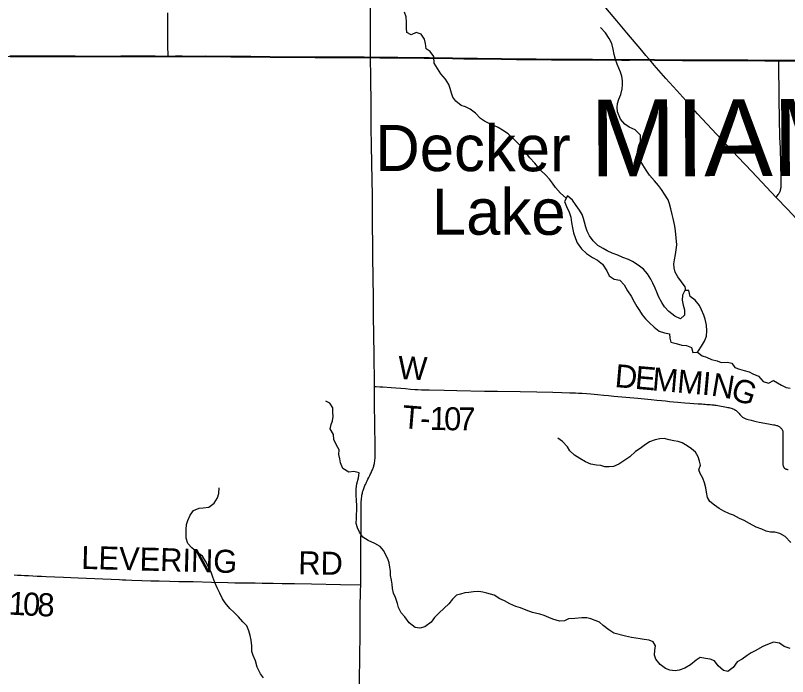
# Model space of a CAD drawing. Extents: x -87 to 2145, y -2128 to 440.
# Drawn here: x 138.4 to 188.6, y 171.2 to 214.2 of the extents above; entities that cross this region are included whole.
import ezdxf

# ---------------------------------------------------------------- set-up
doc = ezdxf.new("R2010")
doc.units = 0
for name, color, linetype in [('GM_X_County_Road', 7, 'Continuous'), ('GM_X_County_Text', 7, 'Continuous'), ('GM_X_Minor_Lake', 7, 'Continuous'), ('GM_X_Minor_Lake_Text', 7, 'Continuous'), ('GM_X_Minor_River', 7, 'Continuous'), ('GM_X_State_Route', 7, 'Continuous'), ('GM_X_Township', 7, 'Continuous'), ('GM_X_Township_Road', 7, 'Continuous'), ('GM_X_Township_Road_Text', 7, 'Continuous'), ('GM_X_Township_Text', 7, 'Continuous'), ('SH_Cut_Line', 7, 'Continuous')]:
    doc.layers.add(name, color=color, linetype=linetype)

msp = doc.modelspace()

# ---------------------------------------------------------------- linework, layer by layer
at = {"layer": 'GM_X_County_Road'}
for points in [[(135.03, 211.568), (135.109, 211.569), (135.519, 211.57), (136.027, 211.566), (136.749, 211.568), (137.175, 211.571), (138.012, 211.566), (139.406, 211.565), (140.879, 211.559), (141.702, 211.555), (142.26, 211.553), (143.31, 211.552), (143.851, 211.547), (144.229, 211.55), (145.229, 211.56), (146.869, 211.562), (147.46, 211.558), (148.231, 211.55), (148.289, 211.551)], [(148.289, 211.551), (148.772, 211.554), (149.215, 211.554), (149.92, 211.552), (150.707, 211.554), (151.199, 211.549), (151.495, 211.548), (151.986, 211.547), (152.38, 211.543), (153.167, 211.535), (153.676, 211.533), (154.446, 211.523), (154.922, 211.517), (156.07, 211.505), (156.726, 211.502), (157.055, 211.502), (157.858, 211.5), (158.498, 211.499), (159.383, 211.487), (159.679, 211.487), (160.17, 211.492), (160.563, 211.492), (161.039, 211.492), (161.46, 211.486)], [(161.46, 211.486), (161.728, 211.483), (162.056, 211.478), (162.81, 211.471), (163.236, 211.467), (163.58, 211.464), (163.859, 211.464), (164.411, 211.459), (164.941, 211.454), (165.284, 211.447), (166.794, 211.423), (167.519, 211.412), (168.248, 211.4), (168.428, 211.4), (168.576, 211.4), (169.133, 211.395), (169.986, 211.381), (170.954, 211.368), (171.381, 211.367), (171.807, 211.365), (172.233, 211.358), (172.643, 211.354), (173.234, 211.348), (173.955, 211.349), (174.349, 211.341), (174.857, 211.336), (175.891, 211.335), (176.547, 211.332), (177.285, 211.332), (177.793, 211.327), (178.302, 211.325), (179.335, 211.332), (179.466, 211.33), (179.622, 211.329)], [(179.622, 211.329), (179.927, 211.325), (181.221, 211.311), (181.745, 211.305), (182.189, 211.305), (182.664, 211.301), (183.533, 211.298), (184.222, 211.296), (185.075, 211.293), (186.01, 211.293), (187.109, 211.284), (187.732, 211.28), (188.051, 211.281)], [(188.051, 211.281), (188.323, 211.282), (189.323, 211.279), (190.176, 211.277), (191.259, 211.274), (192.243, 211.267), (192.834, 211.266), (193.572, 211.263), (194.31, 211.257), (194.654, 211.259)]]:
    msp.add_lwpolyline(points, dxfattribs=at)
at = {"layer": 'GM_X_Minor_Lake'}
for points in [[(175.368, 200.768), (175.314, 201.02), (175.219, 201.274), (175.054, 201.549), (174.829, 201.865), (174.586, 202.212), (174.26, 202.481), (174.071, 202.124), (174.214, 201.789), (174.387, 201.424), (174.48, 201.091), (174.533, 200.748), (174.596, 200.405), (174.669, 200.073), (174.792, 199.708), (174.906, 199.425), (175.169, 199.037), (175.514, 198.728), (175.901, 198.478), (176.219, 198.3), (176.555, 198.031), (176.817, 197.613), (176.971, 197.278), (177.308, 197.07), (177.679, 196.99), (177.954, 196.693), (178.166, 196.317), (178.41, 195.96), (178.603, 195.584), (178.787, 195.288), (178.943, 195.034), (179.127, 194.749), (179.343, 194.493), (179.589, 194.236), (179.904, 193.937), (180.23, 193.689), (180.57, 193.57), (180.91, 193.502), (180.934, 193.221), (180.999, 192.958), (181.339, 192.87), (181.698, 192.771), (182, 192.753), (182.339, 192.615), (182.412, 192.302), (182.734, 192.324)], [(182.734, 192.324), (182.796, 192.393), (182.994, 192.709), (183.172, 193.026), (183.3, 193.364), (183.338, 193.714), (183.306, 194.076), (183.224, 194.459), (183.129, 194.712), (182.976, 195.077), (182.852, 195.361), (182.567, 195.689), (182.241, 195.937), (182.169, 196.32), (181.908, 196.337), (181.74, 196.02), (181.723, 195.689), (181.786, 195.376), (181.87, 195.063), (181.882, 194.722), (181.626, 194.487), (181.247, 194.657), (180.852, 194.958), (180.587, 195.275), (180.402, 195.55), (180.219, 195.896), (180.085, 196.21), (179.97, 196.474), (179.816, 196.798), (179.681, 197.072), (179.468, 197.409), (179.213, 197.726), (178.867, 197.975), (178.5, 198.205), (178.241, 198.341), (177.872, 198.47), (177.533, 198.619), (177.184, 198.758), (176.846, 198.907), (176.588, 199.063), (176.25, 199.262), (175.935, 199.551), (175.691, 199.877), (175.557, 200.192), (175.462, 200.445), (175.368, 200.768), (175.314, 201.02), (175.219, 201.274), (175.054, 201.549), (174.829, 201.865), (174.586, 202.212), (174.26, 202.481), (174.071, 202.124), (174.214, 201.789), (174.387, 201.424), (174.48, 201.091), (174.533, 200.748), (174.596, 200.405), (174.669, 200.073), (174.792, 199.708), (174.906, 199.425), (175.169, 199.037), (175.514, 198.728), (175.901, 198.478), (176.219, 198.3), (176.555, 198.031), (176.817, 197.613), (176.971, 197.278), (177.308, 197.07), (177.679, 196.99), (177.954, 196.693), (178.166, 196.317), (178.41, 195.96), (178.603, 195.584), (178.787, 195.288), (178.943, 195.034), (179.127, 194.749), (179.343, 194.493), (179.589, 194.236), (179.904, 193.937), (180.23, 193.689), (180.57, 193.57), (180.91, 193.502), (180.934, 193.221), (180.999, 192.958), (181.339, 192.87), (181.698, 192.771), (182, 192.753), (182.339, 192.615), (182.412, 192.302), (182.734, 192.324)], [(182.734, 192.324), (182.796, 192.393), (182.994, 192.709), (183.172, 193.026), (183.3, 193.364), (183.338, 193.714), (183.306, 194.076), (183.224, 194.459), (183.129, 194.712), (182.976, 195.077), (182.852, 195.361), (182.567, 195.689), (182.241, 195.937), (182.169, 196.32), (181.908, 196.337), (181.74, 196.02), (181.723, 195.689), (181.786, 195.376), (181.87, 195.063), (181.882, 194.722), (181.626, 194.487), (181.247, 194.657), (180.852, 194.958), (180.587, 195.275), (180.402, 195.55), (180.219, 195.896), (180.085, 196.21), (179.97, 196.474), (179.816, 196.798), (179.681, 197.072), (179.468, 197.409), (179.213, 197.726), (178.867, 197.975), (178.5, 198.205), (178.241, 198.341), (177.872, 198.47), (177.533, 198.619), (177.184, 198.758), (176.846, 198.907), (176.588, 199.063), (176.25, 199.262), (175.935, 199.551), (175.691, 199.877), (175.557, 200.192), (175.462, 200.445), (175.368, 200.768)]]:
    msp.add_lwpolyline(points, dxfattribs=at)
at = {"layer": 'GM_X_Minor_River'}
for points in [[(165.603, 211.11), (165.578, 211.565), (165.344, 211.881), (165.076, 212.058), (165.023, 212.41), (164.969, 212.673), (164.755, 213.009), (164.426, 213.107), (164.111, 212.973), (163.823, 213.12), (163.789, 213.392), (163.787, 213.783), (163.785, 214.145), (163.661, 214.449)], [(177.491, 211.053), (177.395, 211.371), (177.312, 211.694), (177.238, 212.027), (177.146, 212.401), (176.982, 212.736), (176.739, 213.104), (176.424, 213.432)], [(174.187, 202.343), (173.821, 202.652), (173.478, 203.041), (173.292, 203.317), (173.097, 203.573), (172.861, 203.829), (172.507, 204.169), (172.135, 204.619), (171.82, 204.958), (171.517, 205.347), (171.292, 205.633), (171.057, 205.9), (170.712, 206.249), (170.416, 206.517), (170.05, 206.757), (169.752, 206.925), (169.473, 207.062), (169.174, 207.189), (168.876, 207.347), (168.608, 207.524), (168.284, 207.863), (167.938, 208.132), (167.639, 208.27), (167.36, 208.377), (167.004, 208.646), (166.819, 208.912), (166.734, 209.165), (166.64, 209.478), (166.555, 209.741), (166.332, 210.088), (166.038, 210.436), (165.824, 210.773), (165.598, 211.117)], [(181.974, 196.332), (181.933, 196.567), (181.689, 196.884), (181.445, 197.221), (181.28, 197.526), (181.206, 197.808), (181.192, 198.06), (181.237, 198.32), (181.296, 198.679), (181.332, 198.97), (181.37, 199.31), (181.339, 199.752), (181.315, 200.004), (181.263, 200.377), (181.228, 200.628), (181.146, 201.012), (181.081, 201.264), (180.999, 201.638), (180.905, 201.971), (180.81, 202.225), (180.577, 202.602), (180.373, 202.908), (180.187, 203.163), (179.922, 203.461), (179.609, 203.84), (179.385, 204.166), (179.171, 204.513), (178.997, 204.798), (178.892, 205.092), (178.828, 205.365), (178.917, 205.774), (179.014, 206.033), (179.012, 206.435), (178.668, 206.775), (178.27, 206.965), (177.992, 207.142), (177.718, 207.47), (177.517, 207.957), (177.493, 208.239), (177.529, 208.489), (177.616, 208.779), (177.733, 209.077), (177.821, 209.447), (177.857, 209.708), (177.853, 209.969), (177.809, 210.282), (177.725, 210.545), (177.491, 211.053)], [(182.734, 192.324), (183.02, 192.067), (183.32, 191.979), (183.639, 191.841), (184.009, 191.752), (184.268, 191.645), (184.681, 191.675), (184.951, 191.609), (185.146, 191.313), (185.465, 191.215), (185.755, 191.118), (186.075, 191.03), (186.334, 190.913), (186.682, 190.764), (187.006, 190.406), (187.335, 190.287), (187.662, 190.48), (188.178, 190.167), (188.486, 190.009), (188.747, 189.983)], [(162.761, 177.772), (162.757, 178.062), (162.723, 178.323), (162.669, 178.614), (162.574, 178.876), (162.439, 179.14), (162.314, 179.393), (162.079, 179.679), (161.741, 179.867), (161.313, 180.069), (160.956, 180.278), (160.742, 180.603), (160.617, 180.876), (160.513, 181.169), (160.551, 181.507), (160.546, 181.757), (160.572, 182.016), (160.57, 182.356), (160.536, 182.647), (160.514, 183.027), (160.523, 183.417), (160.56, 183.745), (160.67, 184.132), (160.727, 184.461), (160.377, 184.54), (160.044, 184.498), (159.657, 184.738), (159.515, 185.112), (159.47, 185.383), (159.406, 185.664), (159.423, 185.954), (159.239, 186.258), (159.066, 186.623), (159.043, 186.963), (158.84, 187.318), (158.906, 187.606), (158.982, 187.854), (159.019, 188.133), (159.005, 188.404), (159.001, 188.684), (158.817, 188.998), (158.548, 189.125)], [(176.978, 184.852), (176.696, 184.859), (176.427, 184.936), (176.146, 184.963), (175.795, 185.022), (175.436, 185.171), (175.069, 185.391), (174.732, 185.61), (174.417, 185.898), (174.261, 186.162), (173.937, 186.501), (173.64, 186.719)], [(188.796, 179.939), (188.432, 180.309), (188.075, 180.518), (187.745, 180.596), (187.463, 180.603), (187.183, 180.67), (186.914, 180.787), (186.536, 180.937), (186.098, 181.158), (185.75, 181.357), (185.462, 181.494), (185.064, 181.705), (184.805, 181.791), (184.446, 181.96), (184.129, 182.149), (183.832, 182.356), (183.525, 182.604), (183.38, 182.868), (183.307, 183.211), (183.273, 183.492), (183.19, 183.815), (183.066, 184.118), (182.902, 184.413), (182.817, 184.665), (182.914, 184.953), (182.859, 185.225), (182.775, 185.508), (182.59, 185.803), (182.334, 186.03), (182.057, 186.217), (181.719, 186.416), (181.46, 186.512), (181.189, 186.549), (180.889, 186.617), (180.549, 186.695), (180.266, 186.672), (179.963, 186.61), (179.609, 186.478), (179.262, 186.247), (178.986, 186.053), (178.7, 185.85), (178.32, 185.509), (177.932, 185.238), (177.615, 185.016), (177.25, 184.865), (176.978, 184.852)], [(154.486, 171.115), (154.301, 171.39), (154.079, 171.825), (153.978, 172.237), (153.834, 172.581), (153.74, 172.833), (153.738, 173.202), (153.696, 173.583), (153.632, 173.884), (153.538, 174.186), (153.405, 174.509), (153.159, 174.775), (152.864, 175.082), (152.589, 175.379), (152.304, 175.636), (152.01, 175.994), (151.835, 176.258), (151.662, 176.622), (151.479, 176.986), (151.336, 177.329), (151.203, 177.682), (151.108, 177.944), (150.896, 178.379), (150.733, 178.712), (150.519, 179.037), (150.143, 179.327), (149.837, 179.575), (149.582, 179.861), (149.469, 180.203), (149.456, 180.523), (149.461, 180.772), (149.489, 181.101), (149.565, 181.358), (149.723, 181.703), (149.942, 182.017), (150.317, 182.167), (150.569, 182.18), (150.932, 182.221), (151.28, 182.481), (151.499, 182.835), (151.585, 183.112), (151.604, 183.481)], [(188.744, 173.032), (188.354, 173.162), (188.047, 173.37), (187.667, 173.45), (187.281, 173.29), (186.966, 173.158), (186.468, 172.89), (186.213, 172.757), (185.958, 172.583), (185.631, 172.332), (185.295, 172.16), (185.035, 171.797), (184.688, 171.536), (184.417, 171.593), (184.062, 171.912), (183.828, 172.238), (183.559, 172.335), (183.238, 172.374), (182.887, 172.443), (182.632, 172.279), (182.274, 171.979), (181.896, 171.748), (181.542, 171.628), (181.269, 171.575), (180.918, 171.624), (180.649, 171.731), (180.293, 172), (180.019, 172.328), (179.934, 172.59), (179.951, 172.919), (179.998, 173.198), (179.843, 173.462), (179.584, 173.569), (179.263, 173.607), (178.992, 173.654), (178.431, 173.739), (178.041, 173.829), (177.281, 174.039), (176.963, 174.238), (176.598, 174.537), (176.341, 174.744), (176.072, 174.861), (175.793, 174.968), (175.523, 175.025), (175.211, 175.024), (174.737, 174.976), (174.334, 174.957), (174.07, 174.834), (173.748, 174.802), (173.308, 174.944), (173.049, 175.041), (172.75, 175.169), (172.46, 175.256), (172, 175.378), (171.571, 175.52), (171.202, 175.669), (170.903, 175.767), (170.514, 175.927), (170.177, 176.136), (169.868, 176.264), (169.501, 176.494), (169.021, 176.627), (168.761, 176.694), (168.5, 176.73), (168.158, 176.71), (167.856, 176.678), (167.583, 176.645), (167.3, 176.562), (167.047, 176.509), (166.79, 176.246), (166.542, 175.933), (166.244, 175.661), (165.895, 175.341), (165.627, 175.059), (165.409, 174.735), (165, 174.436), (164.666, 174.345), (164.355, 174.403), (163.98, 174.703), (163.686, 175.081), (163.451, 175.347), (163.278, 175.691), (163.203, 175.953), (163.071, 176.346), (162.956, 176.628), (162.883, 176.94), (162.869, 177.21), (162.815, 177.481), (162.761, 177.772)]]:
    msp.add_lwpolyline(points, dxfattribs=at)
at = {"layer": 'GM_X_State_Route'}
for points in [[(179.622, 211.329), (179.557, 211.405), (179.373, 211.624), (179.107, 211.937), (178.127, 213.106), (177.485, 213.875), (176.042, 215.597)], [(189.811, 200.301), (189.755, 200.359), (188.577, 201.611), (187.839, 202.389), (187.207, 203.058), (186.255, 204.065), (185.361, 205.014), (183.961, 206.494), (182.726, 207.815), (181.956, 208.686), (181.37, 209.343), (180.667, 210.129), (179.907, 211.001), (179.622, 211.329)]]:
    msp.add_lwpolyline(points, dxfattribs=at)
at = {"layer": 'GM_X_Township'}
for points in [[(189.317, 211.293), (188.317, 211.296), (188.045, 211.295), (187.726, 211.294), (187.103, 211.298), (186.004, 211.307), (185.069, 211.307), (184.216, 211.31), (183.527, 211.312), (182.658, 211.316), (182.182, 211.32), (181.739, 211.32), (181.215, 211.325), (179.921, 211.34), (179.616, 211.343), (179.459, 211.344), (179.329, 211.346), (178.296, 211.34), (177.787, 211.342), (177.279, 211.346), (176.541, 211.346), (175.885, 211.35), (174.851, 211.35), (174.342, 211.355), (173.949, 211.363), (173.228, 211.362), (172.637, 211.368), (172.227, 211.372), (171.801, 211.379), (171.374, 211.381), (170.948, 211.382), (169.98, 211.395), (169.127, 211.41), (168.57, 211.414), (168.422, 211.415), (168.242, 211.415), (167.512, 211.426), (166.788, 211.437), (165.278, 211.461), (164.935, 211.469), (164.405, 211.474), (163.853, 211.479), (163.574, 211.478), (163.23, 211.481), (162.803, 211.485), (162.049, 211.493), (161.721, 211.497), (161.454, 211.501), (161.445, 230.832)], [(138.005, 211.581), (139.4, 211.58), (140.872, 211.573), (141.696, 211.569), (142.254, 211.567), (143.304, 211.566), (143.845, 211.561), (144.223, 211.564), (145.223, 211.574), (146.863, 211.576), (147.453, 211.572), (148.225, 211.564), (148.283, 211.565), (148.766, 211.568), (149.209, 211.568), (149.914, 211.566), (150.701, 211.568), (151.193, 211.563), (151.489, 211.563), (151.98, 211.561), (152.374, 211.557), (153.161, 211.549), (153.669, 211.547), (154.44, 211.537), (154.916, 211.531), (156.064, 211.519), (156.72, 211.517), (157.048, 211.516), (157.852, 211.515), (158.492, 211.514), (159.377, 211.502), (159.673, 211.502), (160.164, 211.506), (160.557, 211.506), (161.033, 211.507), (161.454, 211.501), (161.721, 211.497), (162.049, 211.493), (162.803, 211.485), (163.23, 211.481), (163.574, 211.478), (163.853, 211.479), (164.405, 211.474), (164.935, 211.469), (165.278, 211.461), (166.788, 211.437), (167.512, 211.426), (168.242, 211.415), (168.422, 211.415), (168.57, 211.414), (169.127, 211.41), (169.98, 211.395), (170.948, 211.382), (171.374, 211.381), (171.801, 211.379), (172.227, 211.372), (172.637, 211.368), (173.228, 211.362), (173.949, 211.363), (174.342, 211.355), (174.851, 211.35), (175.885, 211.35), (176.541, 211.346), (177.279, 211.346), (177.787, 211.342), (178.296, 211.34), (179.329, 211.346), (179.459, 211.344), (179.616, 211.343), (179.921, 211.34), (181.215, 211.325), (181.739, 211.32), (182.182, 211.32), (182.658, 211.316), (183.527, 211.312), (184.216, 211.31), (185.069, 211.307), (186.004, 211.307), (187.103, 211.298), (187.726, 211.294), (188.045, 211.295), (188.317, 211.296), (189.317, 211.293)]]:
    msp.add_lwpolyline(points, dxfattribs=at)
at = {"layer": 'GM_X_Township_Road'}
for points in [[(148.289, 211.551), (148.287, 211.715), (148.283, 212.158), (148.283, 213.158), (148.282, 213.568), (148.272, 214.404)], [(161.711, 190.079), (161.709, 190.266), (161.687, 192.133), (161.659, 194.691), (161.648, 195.826), (161.615, 198.547), (161.587, 201.345), (161.576, 202.482), (161.537, 204.583), (161.511, 205.783), (161.503, 206.911), (161.492, 208.422), (161.474, 210.182), (161.46, 211.486)], [(187.839, 202.389), (187.928, 202.507), (187.973, 202.568), (188.012, 202.629), (188.041, 202.677), (188.069, 202.731), (188.093, 202.783), (188.112, 202.835), (188.125, 202.883), (188.138, 202.939), (188.149, 202.998), (188.156, 203.056), (188.162, 203.13), (188.167, 203.228), (188.16, 203.582), (188.134, 204.571), (188.112, 205.582), (188.088, 206.309), (188.043, 208.751), (188.03, 209.643), (188.019, 210.368), (188.005, 211.141), (188.004, 211.17), (188.007, 211.216), (188.017, 211.239), (188.031, 211.259), (188.051, 211.281)], [(160.821, 177.184), (160.823, 177.308), (160.827, 177.832), (160.824, 179.372), (160.841, 181.388), (160.838, 181.894), (160.84, 182.063), (160.841, 182.183), (160.843, 182.306), (160.845, 182.402), (160.849, 182.499), (160.855, 182.606), (160.862, 182.699), (160.874, 182.819), (160.882, 182.89), (160.891, 182.953), (160.901, 183.018), (160.914, 183.081), (160.925, 183.133), (160.936, 183.183), (160.945, 183.22), (160.958, 183.265), (160.975, 183.32), (160.995, 183.376), (161.016, 183.437), (161.04, 183.504), (161.068, 183.576), (161.092, 183.63), (161.125, 183.699), (161.164, 183.788), (161.197, 183.862), (161.24, 183.951), (161.29, 184.049), (161.342, 184.155), (161.407, 184.283), (161.463, 184.396), (161.494, 184.461), (161.52, 184.518), (161.55, 184.587), (161.578, 184.653), (161.605, 184.719), (161.624, 184.774), (161.646, 184.837), (161.663, 184.893), (161.678, 184.947), (161.693, 185.006), (161.707, 185.062), (161.722, 185.145), (161.733, 185.219), (161.744, 185.311), (161.75, 185.39), (161.756, 185.473), (161.761, 185.557), (161.765, 185.7), (161.767, 185.837), (161.765, 185.991), (161.763, 186.123), (161.759, 186.278), (161.741, 187.505), (161.722, 189.07), (161.711, 190.079)], [(161.711, 190.079), (161.814, 190.076), (162.055, 190.067), (162.261, 190.054), (162.804, 190.017), (163.741, 189.942), (164.054, 189.915), (164.329, 189.894), (164.544, 189.879), (164.768, 189.868), (165.035, 189.859), (165.269, 189.855), (166.237, 189.844), (167.064, 189.831), (168.861, 189.787), (169.713, 189.773), (171.187, 189.748), (172.285, 189.731), (173.312, 189.705), (173.89, 189.69), (174.423, 189.675), (174.785, 189.659), (174.976, 189.651), (175.217, 189.638), (175.499, 189.618), (175.79, 189.597), (176.224, 189.557), (176.637, 189.518), (176.925, 189.49), (177.29, 189.458), (178.843, 189.317), (179.707, 189.232), (180.076, 189.197), (180.373, 189.169), (180.647, 189.141), (180.903, 189.115), (181.165, 189.091), (181.454, 189.065), (181.91, 189.028), (182.22, 189.004), (182.478, 188.982), (182.765, 188.961), (182.904, 188.95), (183.008, 188.943), (183.105, 188.937), (183.218, 188.928), (183.338, 188.919), (183.463, 188.911), (183.553, 188.904), (183.648, 188.896), (183.715, 188.889), (183.785, 188.88), (183.854, 188.872), (183.937, 188.859), (184.039, 188.841), (184.146, 188.822), (184.256, 188.802), (184.397, 188.776), (184.503, 188.757), (184.603, 188.739), (184.694, 188.722), (184.77, 188.705), (184.833, 188.689), (184.904, 188.67), (184.97, 188.65), (185.03, 188.629), (185.087, 188.605), (185.137, 188.579), (185.187, 188.548), (185.232, 188.516), (185.286, 188.472), (185.334, 188.431), (185.371, 188.394), (185.434, 188.323), (185.486, 188.262), (185.547, 188.19), (185.608, 188.127), (185.649, 188.095), (185.689, 188.066), (185.736, 188.038), (185.777, 188.016), (185.827, 187.993), (185.872, 187.975), (185.942, 187.954), (186.013, 187.933), (186.22, 187.884), (186.376, 187.847), (186.532, 187.813), (186.734, 187.767), (186.866, 187.739), (186.979, 187.717), (187.109, 187.693), (187.222, 187.674), (187.333, 187.654), (187.457, 187.632), (187.559, 187.613), (187.667, 187.591), (187.739, 187.576), (187.808, 187.561), (187.856, 187.548), (187.905, 187.532), (187.956, 187.513), (187.993, 187.496), (188.029, 187.476), (188.061, 187.458), (188.095, 187.435), (188.124, 187.41), (188.155, 187.379), (188.187, 187.342), (188.212, 187.305), (188.233, 187.268), (188.253, 187.224), (188.268, 187.185), (188.279, 187.136), (188.283, 187.075), (188.283, 187.012), (188.283, 186.895), (188.281, 186.758), (188.276, 186.332), (188.278, 186.267), (188.275, 186.037), (188.272, 185.141), (188.277, 185.041), (188.281, 184.987), (188.288, 184.944), (188.299, 184.905), (188.313, 184.868), (188.325, 184.842), (188.335, 184.822), (188.351, 184.798), (188.37, 184.777), (188.39, 184.761)], [(188.39, 184.761), (188.411, 184.746), (188.437, 184.731), (188.473, 184.715), (188.502, 184.705), (188.538, 184.694), (188.578, 184.685), (188.631, 184.679)], [(138.27, 177.819), (138.489, 177.808), (138.736, 177.796), (138.956, 177.785), (139.212, 177.772), (139.491, 177.759), (139.778, 177.746), (140.049, 177.735), (140.357, 177.722), (141.481, 177.672), (142.441, 177.628), (145.125, 177.513), (145.318, 177.505), (145.546, 177.496), (145.939, 177.481), (146.579, 177.459), (147.178, 177.442), (147.714, 177.427), (148.4, 177.411), (148.986, 177.401), (149.919, 177.385), (151.104, 177.355), (152.183, 177.327), (152.63, 177.314), (153.111, 177.305), (153.537, 177.301), (153.949, 177.294), (154.405, 177.288), (155.119, 177.279), (155.71, 177.27), (156.507, 177.257), (157.619, 177.236), (159.498, 177.201), (160.821, 177.184)], [(160.664, 158.227), (160.67, 159.24), (160.679, 160.24), (160.691, 161.191), (160.686, 161.863), (160.694, 162.323), (160.699, 162.864), (160.705, 163.175), (160.709, 163.601), (160.711, 164.109), (160.708, 164.797), (160.71, 165.239), (160.713, 166.666), (160.719, 167.583), (160.741, 168.825), (160.734, 169.93), (160.742, 171.043), (160.758, 172.376), (160.782, 174.077), (160.793, 175.687), (160.815, 176.79), (160.821, 177.184)]]:
    msp.add_lwpolyline(points, dxfattribs=at)
at = {"layer": 'GM_X_Township_Text'}
msp.add_lwpolyline([(138.005, 211.581), (139.4, 211.58), (140.872, 211.573), (141.696, 211.569), (142.254, 211.567), (143.304, 211.566), (143.845, 211.561), (144.223, 211.564), (145.223, 211.574), (146.863, 211.576), (147.453, 211.572), (148.225, 211.564), (148.283, 211.565), (148.766, 211.568), (149.209, 211.568), (149.914, 211.566), (150.701, 211.568), (151.193, 211.563), (151.489, 211.563), (151.98, 211.561), (152.374, 211.557), (153.161, 211.549), (153.669, 211.547), (154.44, 211.537), (154.916, 211.531), (156.064, 211.519), (156.72, 211.517), (157.048, 211.516), (157.852, 211.515), (158.492, 211.514), (159.377, 211.502), (159.673, 211.502), (160.164, 211.506), (160.557, 211.506), (161.033, 211.507), (161.454, 211.501), (161.445, 230.832)], dxfattribs=at)
at = {"layer": 'SH_Cut_Line'}
msp.add_lwpolyline([(189.317, 211.293), (188.317, 211.296), (188.045, 211.295), (187.726, 211.294), (187.103, 211.298), (186.004, 211.307), (185.069, 211.307), (184.216, 211.31), (183.527, 211.312), (182.658, 211.316), (182.182, 211.32), (181.739, 211.32), (181.215, 211.325), (179.921, 211.34), (179.616, 211.343), (179.459, 211.344), (179.329, 211.346), (178.296, 211.34), (177.787, 211.342), (177.279, 211.346), (176.541, 211.346), (175.885, 211.35), (174.851, 211.35), (174.342, 211.355), (173.949, 211.363), (173.228, 211.362), (172.637, 211.368), (172.227, 211.372), (171.801, 211.379), (171.374, 211.381), (170.948, 211.382), (169.98, 211.395), (169.127, 211.41), (168.57, 211.414), (168.422, 211.415), (168.242, 211.415), (167.512, 211.426), (166.788, 211.437), (165.278, 211.461), (164.935, 211.469), (164.405, 211.474), (163.853, 211.479), (163.574, 211.478), (163.23, 211.481), (162.803, 211.485), (162.049, 211.493), (161.721, 211.497), (161.454, 211.501), (161.033, 211.507), (160.557, 211.506), (160.164, 211.506), (159.673, 211.502), (159.377, 211.502), (158.492, 211.514), (157.852, 211.515), (157.048, 211.516), (156.72, 211.517), (156.064, 211.519), (154.916, 211.531), (154.44, 211.537), (153.669, 211.547), (153.161, 211.549), (152.374, 211.557), (151.98, 211.561), (151.489, 211.563), (151.193, 211.563), (150.701, 211.568), (149.914, 211.566), (149.209, 211.568), (148.766, 211.568), (148.283, 211.565), (148.225, 211.564), (147.453, 211.572), (146.863, 211.576), (145.223, 211.574), (144.223, 211.564), (143.845, 211.561), (143.304, 211.566), (142.254, 211.567), (141.696, 211.569), (140.872, 211.573), (139.4, 211.58), (138.005, 211.581)], dxfattribs=at)

# ---------------------------------------------------------------- texts
at = {"layer": 'GM_X_County_Text'}
msp.add_text('MIAMI COUNTY', height=5, rotation=0.1487, dxfattribs=at).set_placement((175.742, 203.748))
at = {"layer": 'GM_X_Minor_Lake_Text'}
for s, rotation, p in [('Decker', 359.9103, (161.76, 204.105)), ('Lake', 359.8875, (165.446, 199.965))]:
    msp.add_text(s, height=3.0003, rotation=rotation, dxfattribs=at).set_placement(p)
at = {"layer": 'GM_X_Township_Road_Text'}
for s, rotation, p in [('W', 357.2378, (163.214, 190.579)), ('D', 354.9959, (177.303, 190.05)), ('E', 354.9922, (178.618, 189.935)), ('M', 354.9961, (179.736, 189.837)), ('M', 354.9903, (181.358, 189.695)), ('I', 354.9038, (182.979, 189.553)), ('N', 350.4077, (183.562, 189.502)), ('G', 341.1757, (184.801, 189.298)), ('T', 355.2848, (163.467, 187.379)), ('1', 358.6761, (165.298, 187.261)), ('0', 359.1553, (166.235, 187.239)), ('7', 359.2866, (167.163, 187.226)), ('-', 358.0328, (164.664, 187.283)), ('LEVERING', 358.4115, (142.628, 178.216)), ('RD', 359.0128, (156.748, 177.865)), ('1', 356.9423, (137.892, 175.242)), ('0', 357.1373, (138.821, 175.193)), ('8', 357.9122, (139.766, 175.146))]:
    msp.add_text(s, height=1.5, rotation=rotation, dxfattribs=at).set_placement(p)

doc.saveas('drawing.dxf')
